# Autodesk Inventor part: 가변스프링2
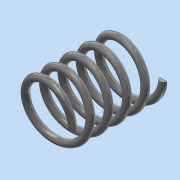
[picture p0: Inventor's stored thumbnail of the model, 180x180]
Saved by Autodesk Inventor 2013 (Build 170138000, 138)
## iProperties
Created: 2018-10
Part Number: 가변스프링2
Material: 스테인리스강
Document SubType Name: Modeling
Designer: Administrator
Density: 8.08 g/cm^3
Mass: 6.28308 g
Surface Area: 15.7652 cm^2
Volume: 0.777609 cm^3
Author: Administrator
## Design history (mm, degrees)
sketch "스케치1"
  geometry: L1 (0, 0)-(0, 26.495); L2 (0, 0)-(8, 0); L3 (0, 26.495)-(8, 26.495); C1 r 1 at (8, 0); 1 further point
  constraints: 6 end point, 2 coincident, 1 centre point, 1 parallel, 1 perpendicular, 1 vertical
  dimensions: "d0" = 26.49536 distance of L1.start L1.end (derived); "d1" = 8 distance of L1.start L2.end; "d2" = 8 distance of L1.end L3.end; "d3" = 2 diameter of C1
feature "코일1" sketch "스케치1" pitch "d4" = 10; turns "d6" = 5; dims "d5" = 26.49536 (= d0), "d7" = 0, angle "d8" = 90 deg, angle "d9" = 90 deg, "d10" = 0, "d11" = 0
sketch "스케치2"
  geometry: L1 (26.495, 12.5)-(0, 12.5); L2 (0, 12.5)-(0, -12.5); L3 (0, -12.5)-(26.495, -12.5); L4 (26.495, -12.5)-(26.495, 12.5); 2 further points
  constraints: 8 end point, 2 parallel, 1 coincident, 1 horizontal, 1 midpoint, 1 perpendicular
  dimensions: "d12" = 25 distance of L3.end L1.start; "d14" = 26.49536 distance of L2.end L3.end (derived)
extrude "돌출1" sketch "스케치2" stored distance "d15" = 20; taper "d16" = 0 deg
node "솔리드1"
